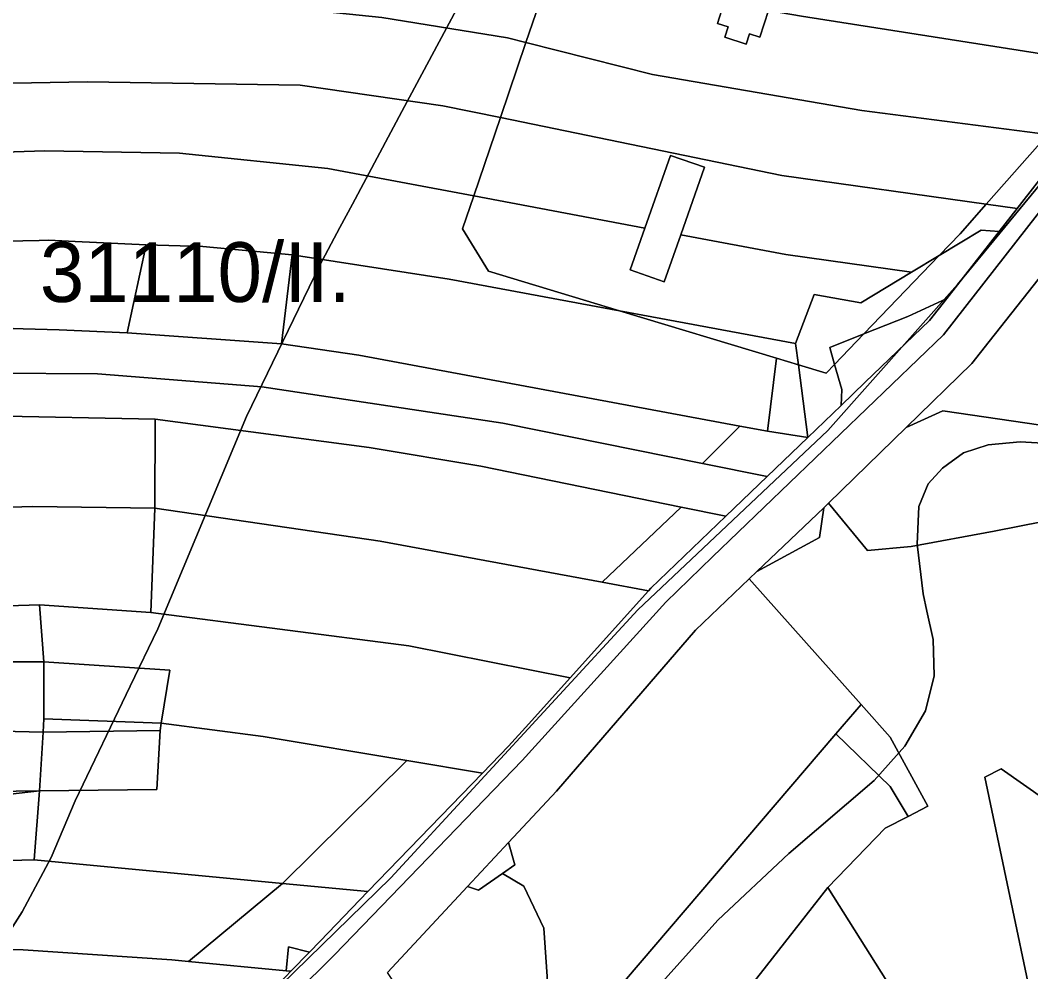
# Model space of a CAD drawing. Extents: x -535894 to -532827, y -1165802 to -1163635.
# Drawn here: x -534145.6 to -533891.9, y -1165184 to -1164945 of the extents above; entities that cross this region are included whole.
import ezdxf

# ---------------------------------------------------------------- set-up
doc = ezdxf.new("R2010")
doc.units = 0
for name, color, linetype in [('BPEJ_s', 7, 'Continuous'), ('orna_s', 7, 'Continuous'), ('ostatni_s', 7, 'Continuous'), ('trav_porost_s', 7, 'Continuous'), ('voda_s', 7, 'Continuous'), ('zahrada_s', 7, 'Continuous')]:
    doc.layers.add(name, color=color, linetype=linetype)

msp = doc.modelspace()

# ---------------------------------------------------------------- linework, layer by layer
at = {"layer": 'BPEJ_s'}
for points in [[(-534128.66, -1165234.701), (-534052.52, -1165160.48), (-533990.56, -1165093.1), (-533942.78, -1165048.02), (-533910.29, -1165011.39), (-533882.731, -1164977.94), (-533858.68, -1164945.769), (-533840.52, -1164915.19)], [(-534023.02, -1164917.81), (-534049.1, -1164966.67), (-534062.187, -1164991.188), (-534065.342, -1164997.098), (-534070.44, -1165006.65), (-534088.76, -1165044.56), (-534111.06, -1165097.92), (-534117.996, -1165112.316), (-534131.852, -1165141.076), (-534137.82, -1165155.34), (-534145.14, -1165168.96), (-534153.03, -1165181.22), (-534158.213, -1165186.838)], [(-534158.213, -1165186.838), (-534153.03, -1165181.22), (-534145.14, -1165168.96), (-534137.82, -1165155.34), (-534131.852, -1165141.076), (-534117.996, -1165112.316), (-534111.06, -1165097.92), (-534088.76, -1165044.56), (-534070.44, -1165006.65), (-534065.342, -1164997.098), (-534062.187, -1164991.188), (-534049.1, -1164966.67), (-534023.02, -1164917.81)], [(-533882.731, -1164977.94), (-533910.29, -1165011.39), (-533942.78, -1165048.02), (-533990.56, -1165093.1), (-534052.52, -1165160.48), (-534128.66, -1165234.701)], [(-533985.872, -1165188.218), (-533970.41, -1165171.07), (-533952.57, -1165154.34), (-533931.15, -1165135.95), (-533923.51, -1165127.35), (-533918.33, -1165118.51), (-533916.1, -1165109.67), (-533916.35, -1165100.556), (-533917.922, -1165093.478), (-533918.89, -1165089.12), (-533920.4, -1165076.62), (-533920, -1165067.14), (-533917.61, -1165061.48), (-533914.03, -1165057.5), (-533912.759, -1165056.577), (-533908.77, -1165053.681), (-533902.587, -1165051.673), (-533894.52, -1165050.89), (-533883.051, -1165051.61)], [(-533883.051, -1165051.61), (-533894.52, -1165050.89), (-533902.587, -1165051.673), (-533908.77, -1165053.681), (-533912.759, -1165056.577), (-533914.03, -1165057.5), (-533917.61, -1165061.48), (-533920, -1165067.14), (-533920.4, -1165076.62), (-533918.89, -1165089.12), (-533917.922, -1165093.478), (-533916.35, -1165100.556), (-533916.1, -1165109.67), (-533918.33, -1165118.51), (-533923.51, -1165127.35), (-533931.15, -1165135.95), (-533952.57, -1165154.34), (-533970.41, -1165171.07), (-533985.872, -1165188.218)]]:
    msp.add_lwpolyline(points, dxfattribs=at)
at = {"layer": 'orna_s'}
for points in [[(-534078.29, -1164923.33), (-534077.35, -1164923.36), (-534012.88, -1164933.73), (-534018.61, -1164950.58), (-534023.28, -1164949.4), (-534054.83, -1164944.3), (-534091.39, -1164940.53), (-534086.44, -1164936.35), (-534082.19, -1164930.46)], [(-534102.62, -1164940.95), (-534091.39, -1164940.53), (-534054.83, -1164944.3), (-534023.28, -1164949.4), (-534018.61, -1164950.58), (-534025.02, -1164969.45), (-534039.47, -1164966.47), (-534075.29, -1164961.33), (-534128.74, -1164960.43), (-534175.69, -1164961.26), (-534214.43, -1164963.28), (-534302.49, -1164968.05), (-534305.74, -1164957.13), (-534302.89, -1164950.93), (-534250.92, -1164946.98), (-534197.15, -1164944.46), (-534154.72, -1164942.88), (-534128.76, -1164941.92)], [(-534175.69, -1164961.26), (-534128.74, -1164960.43), (-534075.29, -1164961.33), (-534039.47, -1164966.47), (-534025.02, -1164969.45), (-534031.7, -1164989.14), (-534068.38, -1164982.26), (-534105.6, -1164978.41), (-534139.49, -1164977.82), (-534213.51, -1164980.26), (-534214.43, -1164963.28)], [(-534139.49, -1164977.82), (-534105.6, -1164978.41), (-534068.38, -1164982.26), (-534031.7, -1164989.14), (-534034.52, -1164997.43), (-534028.02, -1165008.03), (-533995.12, -1165018), (-534037.89, -1165010.01), (-534077.31, -1165003.9), (-534099.72, -1165001.87), (-534114.02, -1165001.45), (-534131.78, -1165000.56), (-534138.54, -1165000.28), (-534140.89, -1165000.32), (-534153.33, -1165000.55), (-534177.53, -1165001), (-534200.18, -1165002.04), (-534218.76, -1165002.89), (-534219.6, -1164983.53), (-534219.73, -1164980.58), (-534213.51, -1164980.26)], [(-534140.89, -1165000.32), (-534138.54, -1165000.28), (-534131.78, -1165000.56), (-534114.02, -1165001.45), (-534118.77, -1165023.54), (-534135.8, -1165022.76), (-534144.89, -1165022.48), (-534152.58, -1165022.25), (-534152.95, -1165011.58), (-534153.33, -1165000.55)], [(-534114.02, -1165001.45), (-534099.72, -1165001.87), (-534077.31, -1165003.9), (-534080, -1165026.25), (-534118.77, -1165023.54)], [(-534077.31, -1165003.9), (-534037.89, -1165010.01), (-533995.12, -1165018), (-533955.72, -1165029.92), (-533958, -1165048.21), (-533964.89, -1165046.93), (-534060.6, -1165029.11), (-534080, -1165026.25)], [(-534152.58, -1165022.25), (-534144.89, -1165022.48), (-534135.8, -1165022.76), (-534118.77, -1165023.54), (-534080, -1165026.25), (-534060.6, -1165029.11), (-533964.89, -1165046.93), (-533974.3, -1165056.33), (-534024.39, -1165046.24), (-534084.94, -1165037.08), (-534126.21, -1165033.79), (-534152.16, -1165033.67), (-534152.25, -1165030.59)], [(-534152.16, -1165033.67), (-534126.21, -1165033.79), (-534084.94, -1165037.08), (-534024.39, -1165046.24), (-533974.3, -1165056.33), (-533958.04, -1165059.61), (-533968.43, -1165069.59), (-533979.67, -1165067.29), (-534029.93, -1165057.03), (-534057.97, -1165052.34), (-534111.7, -1165045.25), (-534153.61, -1165044.37)], [(-534111.7, -1165045.25), (-534057.97, -1165052.34), (-534029.93, -1165057.03), (-533979.67, -1165067.29), (-533999.48, -1165086.16), (-534055.2, -1165075.84), (-534111.79, -1165067.58)], [(-533958, -1165048.21), (-533947.86, -1165049.82), (-533958.04, -1165059.61), (-533974.3, -1165056.33), (-533964.89, -1165046.93)], [(-534111.79, -1165067.58), (-534112.8, -1165093.8), (-534140.8, -1165091.86), (-534180.28, -1165093.1), (-534189.17, -1165093.38), (-534216.42, -1165094.93), (-534226.11, -1165068.82), (-534213.51, -1165068.88), (-534190.1, -1165068.58), (-534142.42, -1165067.13)], [(-534111.79, -1165067.58), (-534055.2, -1165075.84), (-533999.48, -1165086.16), (-533987.84, -1165088.32), (-534007.52, -1165110.17), (-534047.99, -1165102.16), (-534112.8, -1165093.8)], [(-533979.67, -1165067.29), (-533968.43, -1165069.59), (-533987.24, -1165087.66), (-533987.84, -1165088.32), (-533999.48, -1165086.16)], [(-534140.8, -1165091.86), (-534112.8, -1165093.8), (-534047.99, -1165102.16), (-534007.52, -1165110.17), (-534017.92, -1165121.72), (-534023, -1165127.36), (-534029.56, -1165134.15), (-534048.54, -1165130.97), (-534084.59, -1165124.94), (-534110.26, -1165121.6), (-534108.01, -1165108.24), (-534139.68, -1165106.21)], [(-534108.01, -1165108.24), (-534110.26, -1165121.6), (-534139.68, -1165120.52), (-534139.68, -1165106.21)], [(-534139.68, -1165120.52), (-534110.26, -1165121.6), (-534110.44, -1165123.41), (-534139.87, -1165123.82)], [(-534160.98, -1165123.32), (-534139.87, -1165123.82), (-534140.75, -1165138.6), (-534170.15, -1165138.97), (-534169.88, -1165123.1)], [(-534110.44, -1165123.41), (-534110.26, -1165121.6), (-534084.59, -1165124.94), (-534048.54, -1165130.97), (-534079.72, -1165161.87), (-534142.14, -1165155.94), (-534140.75, -1165138.6), (-534111.31, -1165138.24)], [(-534139.87, -1165123.82), (-534110.44, -1165123.41), (-534111.31, -1165138.24), (-534140.75, -1165138.6)], [(-534048.54, -1165130.97), (-534029.56, -1165134.15), (-534058.31, -1165163.91), (-534079.72, -1165161.87)], [(-534170.15, -1165138.97), (-534140.75, -1165138.6), (-534148.07, -1165139.43), (-534189.99, -1165140.23), (-534199.83, -1165141.58), (-534200.14, -1165139.35), (-534192.83, -1165139.25), (-534192.75, -1165139.53), (-534191.54, -1165139.24), (-534190.2, -1165139.22)], [(-534140.75, -1165138.6), (-534142.14, -1165155.94), (-534197.6, -1165157.43), (-534199.83, -1165141.58), (-534189.99, -1165140.23), (-534148.07, -1165139.43)], [(-534197.6, -1165157.43), (-534142.14, -1165155.94), (-534079.72, -1165161.87), (-534103.37, -1165181.48), (-534107.5, -1165181.08), (-534144.9, -1165178.54), (-534196.09, -1165177.34)], [(-534079.72, -1165161.87), (-534058.31, -1165163.91), (-534070.32, -1165176.35), (-534073, -1165179.11), (-534078.28, -1165177.81), (-534078.8, -1165183.83), (-534103.37, -1165181.48)], [(-534196.09, -1165177.34), (-534144.9, -1165178.54), (-534107.5, -1165181.08), (-534103.37, -1165181.48), (-534078.8, -1165183.83), (-534077.66, -1165183.91), (-534078.91, -1165185.19), (-534097.29, -1165204.09), (-534111.65, -1165203.25), (-534176.94, -1165199.42), (-534196.74, -1165197.75)], [(-534078.28, -1165177.81), (-534073, -1165179.11), (-534077.66, -1165183.91), (-534078.8, -1165183.83)]]:
    msp.add_lwpolyline(points, close=True, dxfattribs=at)
at = {"layer": 'ostatni_s'}
for points in [[(-533937.82, -1164879.8), (-533947.31, -1164909.72), (-533942.09, -1164911.38), (-533944.88, -1164920.18), (-533950.1, -1164918.52), (-533951.96, -1164924.41), (-533957.74, -1164942.58), (-533959.85, -1164949.22), (-533962.47, -1164948.39), (-533963.29, -1164950.96), (-533968.66, -1164949.26), (-533967.85, -1164946.68), (-533970.51, -1164945.79), (-533968.93, -1164940.8), (-533963.09, -1164922.39), (-533948.5, -1164876.42)], [(-533932.96, -1164927.87), (-533906.44, -1164932.7), (-533893.29, -1164935.49), (-533882.11, -1164937.86), (-533879.19, -1164938.15), (-533865.26, -1164939.55), (-533858.16, -1164940.26), (-533872.1, -1164956.08), (-533949.39, -1164943.93), (-533957.74, -1164942.58), (-533951.96, -1164924.41)], [(-534012.88, -1164933.73), (-534002.31, -1164935.43), (-534002.59, -1164936.19), (-533995.11, -1164939.02), (-533994.24, -1164936.72), (-533968.93, -1164940.8), (-533970.51, -1164945.79), (-533967.85, -1164946.68), (-533968.66, -1164949.26), (-533963.29, -1164950.96), (-533962.47, -1164948.39), (-533959.85, -1164949.22), (-533957.74, -1164942.58), (-533949.39, -1164943.93), (-533872.1, -1164956.08), (-533887.6, -1164973.66), (-533934.25, -1164967.65), (-533986.88, -1164958.63), (-534018.61, -1164950.58)], [(-534018.61, -1164950.58), (-533986.88, -1164958.63), (-533934.25, -1164967.65), (-533887.6, -1164973.66), (-533903.09, -1164991.22), (-533954.36, -1164984.01), (-534025.02, -1164969.45)], [(-533982.32, -1164978.93), (-533988.74, -1164997.2), (-534031.7, -1164989.14), (-534025.02, -1164969.45), (-533954.36, -1164984.01), (-533903.09, -1164991.22), (-533909.61, -1164998.62), (-533914.87, -1165004.11), (-533921.79, -1165008.29), (-533953.32, -1165003.84), (-533979.75, -1164998.88), (-533973.77, -1164981.91)], [(-533887.6, -1164973.66), (-533881.35, -1164974.47), (-533895.29, -1164992.32), (-533903.09, -1164991.22)], [(-533982.32, -1164978.93), (-533973.77, -1164981.91), (-533979.75, -1164998.88), (-533983.9, -1165010.68), (-533992.43, -1165007.68), (-533988.74, -1164997.2)], [(-534031.7, -1164989.14), (-533988.74, -1164997.2), (-533992.43, -1165007.68), (-533983.9, -1165010.68), (-533979.75, -1164998.88), (-533953.32, -1165003.84), (-533921.79, -1165008.29), (-533934.5, -1165015.99), (-533946.24, -1165013.85), (-533950.91, -1165026.24), (-533995.12, -1165018), (-534028.02, -1165008.03), (-534034.52, -1164997.43)], [(-533903.09, -1164991.22), (-533895.29, -1164992.32), (-533899.75, -1164998.03), (-533904.3, -1164997.71), (-533914.87, -1165004.11), (-533909.61, -1164998.62)], [(-533904.3, -1164997.71), (-533899.75, -1164998.03), (-533912.91, -1165014.89), (-533922.74, -1165019.41), (-533933.76, -1165023.78), (-533914.87, -1165004.11)], [(-533921.79, -1165008.29), (-533914.87, -1165004.11), (-533933.76, -1165023.78), (-533942.33, -1165027.2), (-533941.12, -1165031.45), (-533943.27, -1165033.69), (-533950.22, -1165031.59), (-533950.91, -1165026.24), (-533946.24, -1165013.85), (-533934.5, -1165015.99)], [(-533882.92, -1165006.8), (-533882.85, -1165006.93), (-533877.59, -1165017.13), (-533863.57, -1165044.37), (-533879.05, -1165048.19), (-533913.9, -1165043.12), (-533923.15, -1165047.3), (-533906.69, -1165031.23), (-533902.3, -1165025.67), (-533888.41, -1165008.1), (-533885.29, -1165008.94)], [(-533922.74, -1165019.41), (-533912.91, -1165014.89), (-533917.25, -1165020.44), (-533933.4, -1165035.94), (-533939.43, -1165041.74), (-533939.32, -1165037.78), (-533941.12, -1165031.45), (-533933.76, -1165023.78)], [(-533995.12, -1165018), (-533950.91, -1165026.24), (-533950.22, -1165031.59), (-533955.72, -1165029.92)], [(-533942.33, -1165027.2), (-533933.76, -1165023.78), (-533941.12, -1165031.45)], [(-533955.72, -1165029.92), (-533950.22, -1165031.59), (-533947.86, -1165049.82), (-533958, -1165048.21)], [(-533943.27, -1165033.69), (-533941.12, -1165031.45), (-533939.32, -1165037.78), (-533939.43, -1165041.74), (-533947.86, -1165049.82), (-533950.22, -1165031.59)], [(-533923.15, -1165047.3), (-533913.9, -1165043.12), (-533879.05, -1165048.19), (-533863.57, -1165044.37), (-533833.46, -1165102.84), (-533823.1, -1165108.06), (-533821.44, -1165107.85), (-533816.78, -1165115.9), (-533844.4, -1165103.16), (-533870.09, -1165067.22), (-533901.06, -1165073.37), (-533921.87, -1165077.16), (-533932.89, -1165078.2), (-533942.64, -1165066.34)]]:
    msp.add_lwpolyline(points, close=True, dxfattribs=at)
for points in [[(-533851.83, -1164944.65), (-533913.79, -1165024.04), (-533971.79, -1165079.79), (-533983.52, -1165091.15), (-534019.59, -1165130.92), (-534066.72, -1165179.82), (-534136.8, -1165249.37)], [(-534078.91, -1165185.19), (-534077.66, -1165183.91), (-534073, -1165179.11), (-534070.32, -1165176.35), (-534058.31, -1165163.91), (-534029.56, -1165134.15), (-534023, -1165127.36), (-534017.92, -1165121.72), (-534007.52, -1165110.17), (-533987.84, -1165088.32), (-533987.24, -1165087.66), (-533968.43, -1165069.59), (-533958.04, -1165059.61), (-533947.86, -1165049.82), (-533939.43, -1165041.74), (-533933.4, -1165035.94), (-533917.25, -1165020.44), (-533912.91, -1165014.89), (-533899.75, -1164998.03), (-533895.29, -1164992.32), (-533881.35, -1164974.47)]]:
    msp.add_lwpolyline(points, dxfattribs=at)
at = {"layer": 'trav_porost_s'}
for points in [[(-533885.93, -1165251.42), (-533914.6, -1165207.64), (-533942.82, -1165162.9), (-533928.42, -1165147.92), (-533922.67, -1165144.99), (-533917.7, -1165142.45), (-533927.15, -1165125.06), (-533934.45, -1165116.87), (-533962.53, -1165085.32), (-533960.64, -1165083.51), (-533944.91, -1165074.95), (-533943.82, -1165067.47), (-533942.64, -1165066.34), (-533932.89, -1165078.2), (-533921.87, -1165077.16), (-533901.06, -1165073.37), (-533870.09, -1165067.22)], [(-533864.82, -1165157.28), (-533899.27, -1165133.08), (-533903.4, -1165135.17), (-533879.59, -1165248.35)]]:
    msp.add_lwpolyline(points, dxfattribs=at)
for points in [[(-533944.91, -1165074.95), (-533960.64, -1165083.51), (-533943.82, -1165067.47)], [(-533962.53, -1165085.32), (-533934.45, -1165116.87), (-533940.8, -1165124.3), (-534005.15, -1165199.61), (-534012.92, -1165190.05), (-534014.17, -1165173.12), (-534019.14, -1165162.52), (-534024.54, -1165159.35), (-534021.42, -1165157.14), (-534022.96, -1165151.54), (-534010.91, -1165138.64), (-533976.02, -1165098.2)], [(-533940.8, -1165124.3), (-533934.45, -1165116.87), (-533927.15, -1165125.06), (-533917.7, -1165142.45), (-533922.67, -1165144.99), (-533927.13, -1165137.47)], [(-533940.8, -1165124.3), (-533927.13, -1165137.47), (-533922.67, -1165144.99), (-533928.42, -1165147.92), (-533942.82, -1165162.9), (-533962.19, -1165187.57), (-533989.71, -1165212.03), (-534005.15, -1165199.61)], [(-533903.4, -1165135.17), (-533899.27, -1165133.08), (-533864.82, -1165157.28), (-533806.07, -1165212.59), (-533879.59, -1165248.35)], [(-534021.42, -1165157.14), (-534024.54, -1165159.35), (-534030.52, -1165163.57), (-534033.26, -1165162.58), (-534022.96, -1165151.54)], [(-534024.54, -1165159.35), (-534019.14, -1165162.52), (-534014.17, -1165173.12), (-534012.92, -1165190.05), (-534005.15, -1165199.61), (-533989.71, -1165212.03), (-533992.77, -1165214.76), (-533945.33, -1165285.03), (-533972.2, -1165304.55), (-534018.44, -1165236.03), (-534020.37, -1165233.16), (-534053.42, -1165184.18), (-534033.26, -1165162.58), (-534030.52, -1165163.57)], [(-533962.19, -1165187.57), (-533942.82, -1165162.9), (-533914.6, -1165207.64), (-533885.93, -1165251.42), (-533945.33, -1165285.03), (-533992.77, -1165214.76), (-533989.71, -1165212.03)]]:
    msp.add_lwpolyline(points, close=True, dxfattribs=at)
at = {"layer": 'voda_s'}
for points in [[(-533913.79, -1165024.04), (-533851.83, -1164944.65), (-533849.69, -1164940.46), (-533843.98, -1164906.47), (-533838.18, -1164893.83), (-533831.54, -1164880.79), (-533827.73, -1164876.4), (-533824.38, -1164874.44), (-533814.12, -1164868.44), (-533807.19, -1164864.79), (-533772.11, -1164858.69), (-533727.16, -1164854.1), (-533726.9, -1164854), (-533723.4, -1164852.55), (-533719.59, -1164850.96), (-533704.29, -1164842.98), (-533700.79, -1164841.16), (-533699.02, -1164840.23), (-533671.59, -1164831.22), (-533632.04, -1164823.51)], [(-533888.41, -1165008.1), (-533902.3, -1165025.67), (-533906.69, -1165031.23), (-533923.15, -1165047.3), (-533942.64, -1165066.34), (-533943.82, -1165067.47), (-533960.64, -1165083.51), (-533962.53, -1165085.32), (-533976.02, -1165098.2), (-534010.91, -1165138.64), (-534022.96, -1165151.54), (-534033.26, -1165162.58), (-534053.42, -1165184.18)], [(-534136.8, -1165249.37), (-534066.72, -1165179.82), (-534019.59, -1165130.92), (-533983.52, -1165091.15), (-533971.79, -1165079.79), (-533913.79, -1165024.04)]]:
    msp.add_lwpolyline(points, dxfattribs=at)
at = {"layer": 'zahrada_s'}
for points in [[(-534111.7, -1165045.25), (-534111.79, -1165067.58), (-534142.42, -1165067.13), (-534190.1, -1165068.58), (-534213.51, -1165068.88), (-534215.59, -1165063.71), (-534190.8, -1165063.47), (-534193.26, -1165045.43), (-534153.61, -1165044.37)], [(-534180.28, -1165093.1), (-534140.8, -1165091.86), (-534139.68, -1165106.21), (-534159.84, -1165106.18), (-534179.27, -1165106.14)], [(-534139.68, -1165106.21), (-534139.68, -1165120.52), (-534139.87, -1165123.82), (-534160.98, -1165123.32), (-534160.14, -1165110.71), (-534159.84, -1165106.18)]]:
    msp.add_lwpolyline(points, close=True, dxfattribs=at)

# ---------------------------------------------------------------- texts
at = {"layer": 'BPEJ_s'}
msp.add_text('31110/II.', height=15, dxfattribs=at).set_placement((-534140.68, -1165015.769))

doc.saveas('drawing.dxf')
